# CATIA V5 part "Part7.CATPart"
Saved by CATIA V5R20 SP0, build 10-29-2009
Part number: 3JT7.5X2X11.5
Revision: ANY
Definition: UNKNOWN
Nomenclature: 3JT7.5X2X11.5
Source: Unknown
Bounding box of the stored display mesh (mm): x -5.75 to 5.75, y -5.75 to 5.75, z -1 to 1
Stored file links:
  C:\Users\Utente\Desktop\IO LAVORO\3D X SITO CF\CUMSA\3D files PW\pw060822\pw060822_injection\Part7.CATPart
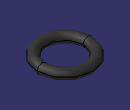
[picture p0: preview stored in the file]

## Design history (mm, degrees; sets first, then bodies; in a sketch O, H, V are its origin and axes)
Body1 "Revolución1" (main body)
  Solid1: solid without history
